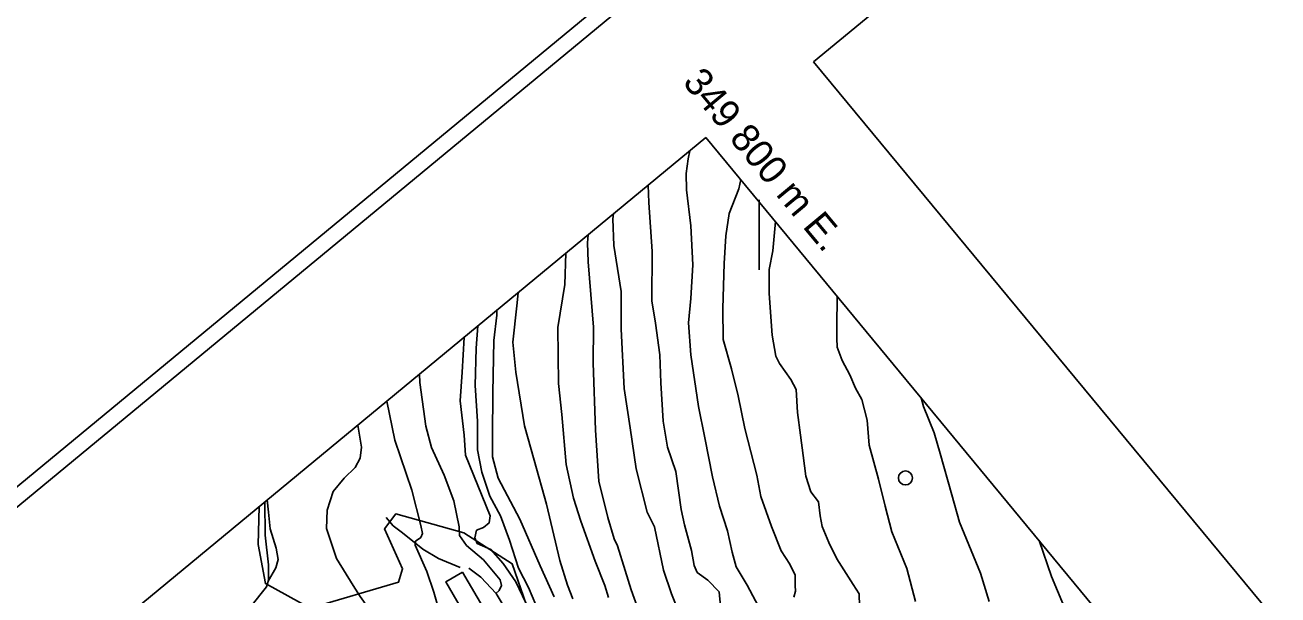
# Model space of a CAD drawing. Extents: x 347059 to 352153, y 6073752 to 6078601.
# Drawn here: x 349642.8 to 349911.2, y 6077877.3 to 6077999.4 of the extents above; entities that cross this region are included whole.
import ezdxf

# ---------------------------------------------------------------- set-up
doc = ezdxf.new("R2010")
doc.units = 0
for name, color, linetype in [('Level 1', 7, 'Continuous'), ('Level 10', 7, 'Continuous'), ('Level 2', 7, 'Continuous'), ('Level 21', 7, 'Continuous'), ('Level 22', 7, 'Continuous'), ('Level 31', 7, 'Continuous'), ('Level 36', 7, 'Continuous'), ('Level 4', 7, 'Continuous'), ('Level 44', 7, 'Continuous'), ('Level 60', 7, 'Continuous'), ('Level 61', 7, 'Continuous')]:
    doc.layers.add(name, color=color, linetype=linetype)

msp = doc.modelspace()

# ---------------------------------------------------------------- linework, layer by layer
at = {"layer": 'Level 1'}
for points in [[(349776.04, 6077895.04), (349773.67, 6077904.33), (349772.42, 6077913.09), (349771.14, 6077921.55), (349770.5, 6077934.26), (349770.49, 6077942.33), (349768.91, 6077952.13), (349768.68, 6077957.89), (349768.82, 6077958.92)], [(349833.56, 6077875.84), (349831.65, 6077882.93), (349828.44, 6077890.79), (349827.03, 6077896.32), (349825.57, 6077902.08), (349823.61, 6077909.4), (349823.19, 6077914.7), (349822.03, 6077919.13), (349820.68, 6077921.56), (349819.44, 6077924.48), (349817.85, 6077927.5), (349816.76, 6077930.41), (349816.66, 6077932.29), (349816.68, 6077934.67), (349816.72, 6077941.31)], [(349748.51, 6077883.03), (349746.53, 6077888.99), (349744.62, 6077894.21), (349742.31, 6077898.44), (349740.62, 6077903.56), (349739.7, 6077908.4), (349739.72, 6077914.55), (349739.22, 6077922.13), (349739.43, 6077930.17), (349739.79, 6077934.93)], [(349785.64, 6077866.58), (349781.24, 6077877.5), (349779.55, 6077882.59), (349777.62, 6077891.85), (349776.04, 6077895.04)], [(349752.99, 6077873.27), (349750.6, 6077878.9), (349748.51, 6077883.03)]]:
    msp.add_lwpolyline(points, dxfattribs=at)
at = {"layer": 'Level 10'}
msp.add_lwpolyline([(349694.45, 6077879.03), (349691.1, 6077874.78), (349690.17, 6077874.98), (349683.1, 6077867.67), (349685, 6077838.24), (349696.78, 6077840.31), (349697.63, 6077834.04), (349685.29, 6077831.12), (349685, 6077829.74), (349686.27, 6077820.99), (349694.9, 6077816.39), (349691.65, 6077797.93), (349688.41, 6077779.72), (349684.95, 6077758.88), (349695.08, 6077757.75), (349699.35, 6077779.33), (349712.5, 6077776.4), (349715.94, 6077761.82), (349720.05, 6077744.62), (349714.13, 6077728.26), (349708.19, 6077710.81)], dxfattribs=at)
at = {"layer": 'Level 2'}
for points in [[(349800.44, 6077873.7), (349797.43, 6077879.39), (349795.12, 6077883.29), (349794.26, 6077886.41), (349793.26, 6077890.99), (349791.53, 6077896.29), (349790.04, 6077902.58), (349788.39, 6077910.98), (349787.01, 6077917.63), (349785.41, 6077928.71), (349784.93, 6077935.56), (349785.38, 6077940.81), (349785.8, 6077948.02), (349785.39, 6077956.39), (349784.48, 6077964.08), (349784.38, 6077967.57), (349784.84, 6077970.72), (349785.2, 6077972.46)], [(349807.43, 6077876.8), (349807.85, 6077878.06), (349807.75, 6077879.3), (349807.75, 6077881.55), (349806.6, 6077883.89), (349804.78, 6077886.73), (349802.68, 6077891.98), (349800.4, 6077898.4), (349799.54, 6077902.96), (349796.97, 6077912.95), (349795.55, 6077919.95), (349794.09, 6077925.72), (349792.31, 6077932.03), (349792.25, 6077938.69), (349792.54, 6077948.29), (349792.92, 6077954.26), (349793.61, 6077959.05), (349795.65, 6077964.3), (349796.08, 6077966.28)], [(349793.23, 6077871.05), (349791.73, 6077874.87), (349791.45, 6077877.94), (349789.07, 6077880.47), (349786.76, 6077882.12), (349786.1, 6077883.56), (349785.54, 6077886.8), (349784.04, 6077892.3), (349783.35, 6077895.56), (349782.73, 6077899.68), (349782.18, 6077903.72), (349780.37, 6077908.95), (349779.46, 6077914.55), (349778.96, 6077922.72), (349778.76, 6077928.76), (349777.82, 6077935.52), (349777.06, 6077940.3), (349777.08, 6077950.9), (349776.37, 6077961.41), (349776.28, 6077965.09)], [(349821.53, 6077874.86), (349821.44, 6077877.54), (349820.18, 6077879.53), (349816.66, 6077885.04), (349814.97, 6077888.51), (349813.56, 6077891.96), (349813.13, 6077894.23), (349812.78, 6077897.23), (349811.1, 6077899.4), (349810.05, 6077902.74), (349809.47, 6077907.13), (349808.89, 6077911.51), (349808.28, 6077916.41), (349807.97, 6077921.28), (349806.8, 6077923.47), (349804.38, 6077926.86), (349803.59, 6077928.45), (349802.8, 6077932.92), (349802.16, 6077941.87), (349802.16, 6077947), (349802.93, 6077951.05), (349803.5, 6077957.31)], [(349767.62, 6077893.87), (349765.68, 6077901.69), (349764.94, 6077912.6), (349764.46, 6077927.05), (349764.56, 6077934.68), (349763.39, 6077948.69), (349763.27, 6077952.7), (349763.38, 6077954.42)], [(349761.84, 6077893.06), (349760.28, 6077898), (349758.72, 6077905.21), (349757.74, 6077915.94), (349757.07, 6077922.56), (349756.87, 6077934.6), (349758.37, 6077943.8), (349758.63, 6077950.5)], [(349758.95, 6077879.35), (349757.35, 6077884.67), (349754.44, 6077896.75), (349751.85, 6077906.18), (349749.79, 6077913.51), (349747.92, 6077924.99), (349747.25, 6077931.47), (349748.09, 6077939.21), (349748.37, 6077942.02)], [(349756.14, 6077876.85), (349753.13, 6077883.55), (349748.75, 6077893.51), (349744.12, 6077902.32), (349742.88, 6077906.88), (349742.88, 6077911.27), (349743, 6077920.69), (349743.07, 6077924.34), (349743.22, 6077931.78), (349743.83, 6077937.21), (349743.8, 6077938.24)], [(349739.51, 6077891.18), (349740.96, 6077891.72), (349742.16, 6077892.71), (349742.39, 6077894.23), (349737.12, 6077907.23), (349736.81, 6077911.51), (349735.99, 6077918.84), (349736.38, 6077925.04), (349736.8, 6077932.46)], [(349737.31, 6077887.89), (349735.82, 6077890), (349735.78, 6077891.84), (349734.64, 6077897.44), (349732.53, 6077902.92), (349729.87, 6077908.87), (349728.63, 6077913.46), (349727.34, 6077922.82), (349727.27, 6077924.59)], [(349727.57, 6077892.15), (349725.59, 6077899.75), (349722, 6077910.43), (349720.26, 6077918.79)], [(349849.3, 6077875.84), (349847.44, 6077881.91), (349842.95, 6077892.89), (349841.28, 6077898.73), (349838.82, 6077907.59), (349837.52, 6077912.03), (349835.25, 6077917.63), (349834.75, 6077919.49)], [(349713.02, 6077879.3), (349709.45, 6077885.06), (349707.35, 6077891.51), (349707.45, 6077895.47), (349708.79, 6077899.41), (349711.15, 6077902.29), (349713.45, 6077904.6), (349714.53, 6077906.57), (349714.84, 6077908.97), (349714.04, 6077913.66)], [(349694.82, 6077880.23), (349696.51, 6077883.11), (349696.98, 6077884.84), (349696.56, 6077887.31), (349695.27, 6077891.47), (349694.88, 6077895.05), (349694.66, 6077897.64)], [(349767.77, 6077876.72), (349766.99, 6077879.27), (349764.88, 6077884.55), (349761.84, 6077893.06)], [(349774.21, 6077874.01), (349772.59, 6077878.37), (349771.32, 6077882.49), (349769.72, 6077887.8), (349768.99, 6077889.31), (349767.62, 6077893.87)], [(349737.03, 6077845.65), (349736.24, 6077849.1), (349734.13, 6077861.42), (349732.92, 6077867.11), (349731.85, 6077872.65), (349730.37, 6077877.85), (349728.82, 6077882.33), (349726.34, 6077887.91), (349726.43, 6077888.79), (349727.54, 6077889.57), (349727.92, 6077890.42), (349727.57, 6077892.15)], [(349739.51, 6077891.18), (349739.12, 6077889.53), (349739.59, 6077888.31), (349742.56, 6077887.03), (349745.2, 6077884.01), (349747.91, 6077880.11), (349751.44, 6077872.61)], [(349743.64, 6077877.61), (349744.35, 6077878.25), (349744.86, 6077879.3), (349744.54, 6077880.5), (349740.98, 6077884.78), (349737.31, 6077887.89)], [(349952.21, 6077714.01), (349940.56, 6077731.19), (349933.43, 6077744.22), (349930.23, 6077752.86), (349926.1, 6077763.89), (349922.2, 6077771.44), (349920.24, 6077777.95), (349920.11, 6077782.58), (349917.9, 6077790.98), (349914.87, 6077795.57), (349908.97, 6077803.29), (349901.21, 6077811.32), (349893.29, 6077819.22), (349889.43, 6077824.16), (349884.43, 6077836.56), (349878.15, 6077846.32), (349873.77, 6077854.77), (349870.11, 6077864.59), (349866.15, 6077872.85), (349862.63, 6077881.22), (349860, 6077888.93)], [(349720.14, 6077841.67), (349720.21, 6077842.36), (349719.84, 6077844.46), (349718.59, 6077845.97), (349715.99, 6077846.64), (349714.94, 6077847.25), (349714.35, 6077847.96), (349713.75, 6077851.62), (349714.03, 6077856.68), (349714.54, 6077861.13), (349716.15, 6077867.69), (349716.31, 6077870.77), (349716.51, 6077872.81), (349716.11, 6077874.76), (349714.56, 6077876.96), (349713.02, 6077879.3)], [(349758.95, 6077879.35), (349760.13, 6077876.47)]]:
    msp.add_lwpolyline(points, dxfattribs=at)
at = {"layer": 'Level 21'}
msp.add_lwpolyline([(349737.81, 6077883.04), (349740.4, 6077881.12), (349743.66, 6077877.58), (349746.75, 6077872.46)], dxfattribs=at)
at = {"layer": 'Level 22'}
msp.add_lwpolyline([(349735.96, 6077883.14), (349731.32, 6077885.07), (349727.96, 6077887.09), (349723.62, 6077890.57), (349721.65, 6077892.1), (349720.12, 6077893.84)], dxfattribs=at)
at = {"layer": 'Level 31'}
msp.add_lwpolyline([(349736.47, 6077882.15), (349743.96, 6077869.35), (349740.47, 6077867.3), (349738.84, 6077870.09), (349737.71, 6077869.42), (349736.3, 6077871.82), (349737.35, 6077872.44), (349732.9, 6077880.06), (349736.47, 6077882.15)], dxfattribs=at)
at = {"layer": 'Level 36'}
msp.add_circle((349831.37, 6077902.34), 1.5, dxfattribs=at)
at = {"layer": 'Level 4'}
msp.add_lwpolyline([(349694.12, 6077897.2), (349694.17, 6077890.12), (349694.89, 6077883.73), (349694.9, 6077880.46), (349694.45, 6077879.03)], dxfattribs=at)
at = {"layer": 'Level 44'}
msp.add_lwpolyline([(349750.22, 6077875.1), (349747.15, 6077883.96), (349736.78, 6077890.61), (349722.2, 6077894.69), (349719.78, 6077891.44), (349723.64, 6077882.88), (349722.73, 6077880), (349703.83, 6077874.42), (349694.25, 6077879.71), (349692.68, 6077888.09), (349692.88, 6077896.17)], dxfattribs=at)
at = {"layer": 'Level 60'}
msp.add_line((349800, 6077961.98), (349800, 6077946.98), dxfattribs=at)
for points in [[(350488.49, 6078600.77), (347058.77, 6075766.69)], [(350488.06, 6078596.06), (347063.49, 6075766.23)]]:
    msp.add_lwpolyline(points, dxfattribs=at)
for points in [[(349811.7, 6077991.51), (350486.88, 6078550.39), (352105.73, 6076594.68), (351430.55, 6076035.79)], [(347109.95, 6075761.81), (348728.53, 6073803.05), (351407.22, 6076016.53), (349788.63, 6077975.29)]]:
    msp.add_lwpolyline(points, close=True, dxfattribs=at)

# ---------------------------------------------------------------- texts
at = {"layer": 'Level 61'}
msp.add_text('349 800 m E. ', height=6.0001, rotation=309.813, dxfattribs=at).set_placement((349783.46, 6077987.05))

doc.saveas('drawing.dxf')
